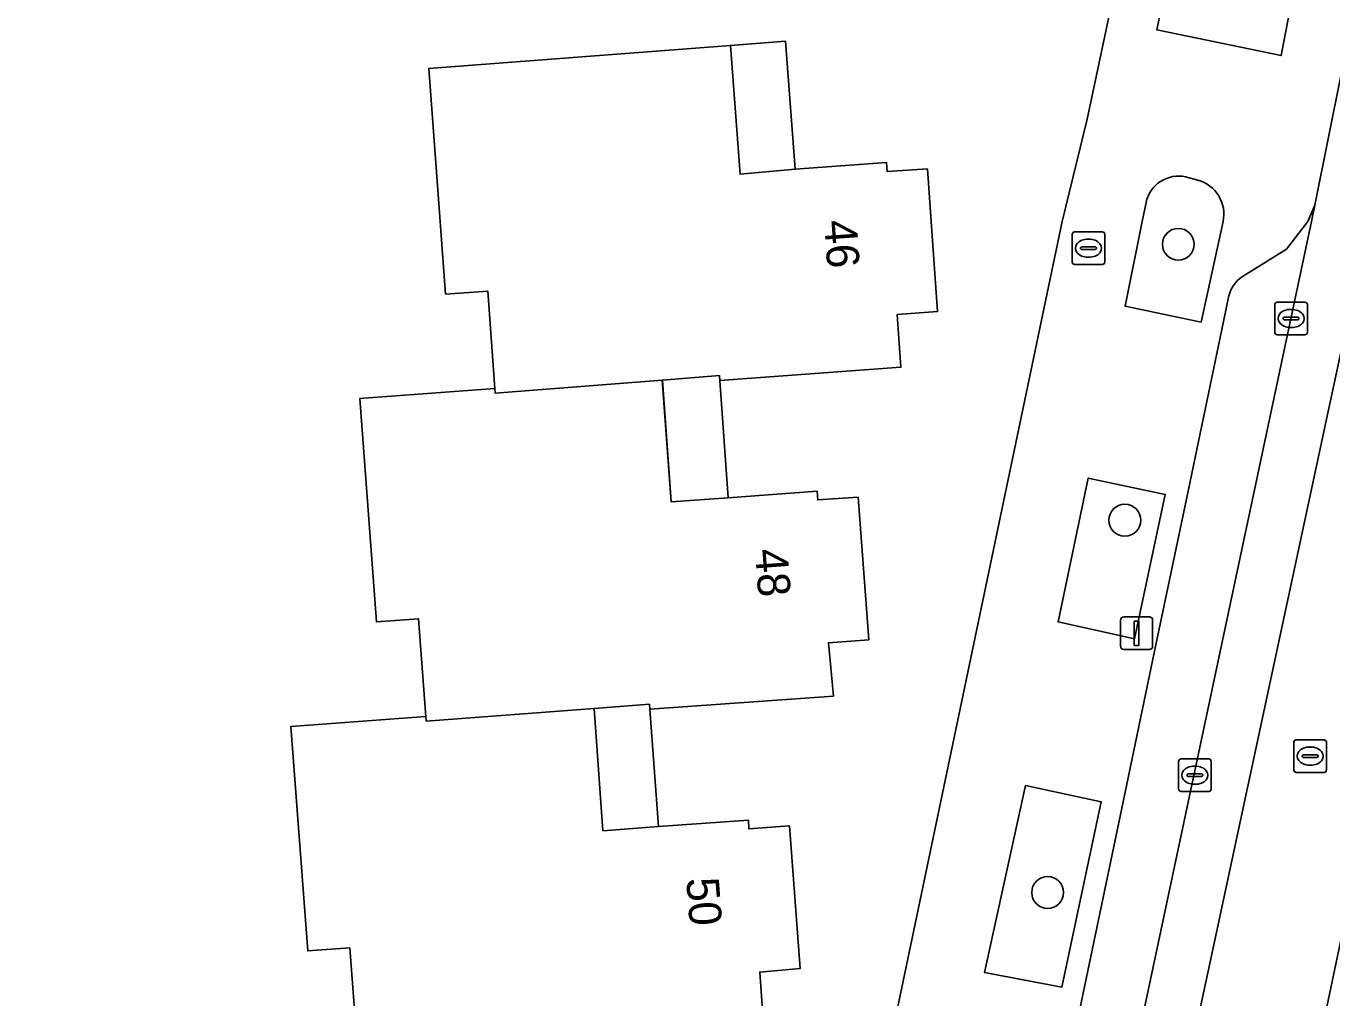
# Model space of a CAD drawing. Extents: x 163426 to 164192, y 380329 to 381641.
# Drawn here: x 163845.09 to 163885.21, y 380976.16 to 381006 of the extents above; entities that cross this region are included whole.
import ezdxf

# ---------------------------------------------------------------- set-up
doc = ezdxf.new("R2010")
doc.units = 0
for name, color, linetype in [('IMGEO_Boom', 7, 'Continuous'), ('IMGEO_Brandkraan', 7, 'Continuous'), ('IMGEO_Erf', 7, 'Continuous'), ('IMGEO_Groenvoorziening', 7, 'Continuous'), ('IMGEO_Kolk', 7, 'Continuous'), ('IMGEO_Lichtmast', 7, 'Continuous'), ('IMGEO_Pand', 7, 'Continuous'), ('IMGEO_Pand_nummerreeks', 7, 'Continuous'), ('IMGEO_Pand_overbouw', 7, 'Continuous'), ('IMGEO_Parkeervlak_open', 7, 'Continuous'), ('IMGEO_Rijbaan_lokaal_open', 7, 'Continuous'), ('IMGEO_Rioolput', 7, 'Continuous'), ('IMGEO_Voetpad_open', 7, 'Continuous')]:
    doc.layers.add(name, color=color, linetype=linetype)

msp = doc.modelspace()

# ---------------------------------------------------------------- linework, layer by layer
at = {"layer": 'IMGEO_Boom'}
for centre in [(163880.488, 380999.302), (163878.846, 380990.828), (163876.474, 380979.396)]:
    msp.add_circle(centre, 0.489, dxfattribs=at)
at = {"layer": 'IMGEO_Brandkraan'}
for p, q in [((163877.229, 380998.756), (163877.229, 380999.608)), ((163877.304, 380999.682), (163878.156, 380999.682)), ((163877.717, 380999.462), (163877.742, 380999.462)), ((163878.23, 380999.608), (163878.23, 380998.756)), ((163877.488, 380999.176), (163877.488, 380999.188)), ((163877.926, 380999.139), (163877.528, 380999.139)), ((163877.531, 380999.225), (163877.929, 380999.225)), ((163877.972, 380999.188), (163877.972, 380999.176)), ((163878.156, 380998.682), (163877.304, 380998.682)), ((163877.74, 380998.902), (163877.715, 380998.902))]:
    msp.add_line(p, q, dxfattribs=at)
for points in [[(163877.229, 380998.756), (163877.229, 380999.608)], [(163877.304, 380999.682), (163878.156, 380999.682)], [(163878.23, 380999.608), (163878.23, 380998.756)], [(163878.156, 380998.682), (163877.304, 380998.682)]]:
    msp.add_lwpolyline(points, dxfattribs=at)
for centre, radius, start, end in [((163877.306, 380999.606), 0.0765, 91.552, 178.448), ((163877.306, 380999.606), 0.0765, 91.552, 178.448), ((163878.154, 380999.606), 0.0765, 1.552, 88.448), ((163878.154, 380999.606), 0.0765, 1.552, 88.448), ((163877.528, 380999.185), 0.0403, 85.8775, 175.7526), ((163877.525, 380999.175), 0.0366, 178.938, 274.7102), ((163877.929, 380999.182), 0.043, 264.8664, 352.4533), ((163877.933, 380999.187), 0.0386, 1.7309, 96.639), ((163877.306, 380998.758), 0.0765, 181.552, 268.448), ((163877.306, 380998.758), 0.0765, 181.552, 268.448), ((163878.154, 380998.758), 0.0765, 271.552, 358.448), ((163878.154, 380998.758), 0.0765, 271.552, 358.448)]:
    msp.add_arc(centre, radius, start, end, dxfattribs=at)
for centre, major_axis, ratio, start_param, end_param in [((163877.716, 380999.182), (-0.387, 0.002), 0.722429, 4.712389, 7.853982), ((163877.741, 380999.182), (-0.39, 0.002), 0.717154, 1.570796, 4.712389)]:
    msp.add_ellipse(centre, major_axis=major_axis, ratio=ratio, start_param=start_param, end_param=end_param, dxfattribs=at)
at = {"layer": 'IMGEO_Erf'}
for points in [[(163876.92, 381000), (163877.694, 381003.139), (163878.337, 381006.181), (163878.606, 381007.454), (163876.484, 381007.934), (163866.201, 381009.23), (163857.633, 381009.637), (163842.019, 381008.688), (163839.157, 381008.481), (163804.103, 381005.949), (163804.54, 381000), (163809.124, 380937.572)], [(163855.262, 380974.705), (163855.037, 380977.702), (163853.743, 380977.604), (163853.224, 380984.493), (163857.375, 380984.806), (163857.149, 380987.803), (163855.855, 380987.705), (163855.347, 380994.567), (163859.496, 380994.875), (163859.275, 380997.867), (163857.978, 380997.771), (163857.834, 380999.717), (163857.813, 381000), (163857.465, 381004.703), (163866.73, 381005.41), (163867.025, 381001.45), (163868.714, 381001.607), (163871.527, 381001.818), (163871.543, 381001.538), (163872.78, 381001.617), (163872.894, 381000), (163873.088, 380997.235), (163871.849, 380997.145), (163871.967, 380995.526), (163866.4, 380995.119), (163866.389, 380995.269), (163864.642, 380995.131), (163864.637, 380995.131), (163864.91, 380991.393), (163866.663, 380991.521), (163869.391, 380991.72), (163869.411, 380991.451), (163870.65, 380991.541), (163870.979, 380987.158), (163869.739, 380987.068), (163869.895, 380985.426), (163864.257, 380985.029), (163864.246, 380985.179), (163862.54, 380985.049), (163862.813, 380981.295), (163864.52, 380981.419), (163867.28, 380981.62), (163867.3, 380981.35), (163868.54, 380981.44), (163868.868, 380977.059), (163867.632, 380976.955), (163867.744, 380975.339)], [(163865.188, 380943.961), (163876.92, 381000)]]:
    msp.add_lwpolyline(points, dxfattribs=at)
at = {"layer": 'IMGEO_Groenvoorziening'}
for points in [[(163883.65, 381005.095), (163884.459, 381009.317), (163880.64, 381009.791), (163879.831, 381005.887)], [(163879.148, 380987.189), (163880.09, 380991.621), (163877.721, 380992.125), (163876.796, 380987.708)], [(163876.909, 380976.494), (163878.124, 380982.184), (163875.792, 380982.681), (163874.533, 380976.942)]]:
    msp.add_lwpolyline(points, close=True, dxfattribs=at)
for points in [[(163881.088, 381001.269), (163880.713, 381001.374)], [(163879.497, 381000.588), (163879.378, 381000), (163878.853, 380997.401), (163881.191, 380996.913), (163881.865, 381000)]]:
    msp.add_lwpolyline(points, dxfattribs=at)
for centre, radius, start, end in [((163880.498, 381000.374), 1.023, 77.8442, 167.9115), ((163880.812, 381000.228), 1.077, 347.7899, 75.1678)]:
    msp.add_arc(centre, radius, start, end, dxfattribs=at)
at = {"layer": 'IMGEO_Kolk'}
for p, q in [((163883.452, 380996.598), (163883.452, 380997.45)), ((163883.527, 380997.524), (163884.379, 380997.524)), ((163884.453, 380997.45), (163884.453, 380996.598)), ((163883.711, 380997.018), (163883.711, 380997.03)), ((163883.754, 380997.067), (163884.152, 380997.067)), ((163883.94, 380997.304), (163883.965, 380997.304)), ((163884.195, 380997.03), (163884.195, 380997.018)), ((163884.149, 380996.981), (163883.751, 380996.981)), ((163883.963, 380996.744), (163883.938, 380996.744)), ((163884.379, 380996.524), (163883.527, 380996.524)), ((163880.498, 380982.573), (163880.498, 380983.425)), ((163880.573, 380983.499), (163881.425, 380983.499)), ((163881.499, 380983.425), (163881.499, 380982.573)), ((163880.757, 380982.993), (163880.757, 380983.005)), ((163880.8, 380983.042), (163881.198, 380983.042)), ((163880.986, 380983.279), (163881.011, 380983.279)), ((163881.241, 380983.005), (163881.241, 380982.993)), ((163881.195, 380982.956), (163880.797, 380982.956)), ((163881.009, 380982.719), (163880.984, 380982.719)), ((163881.425, 380982.499), (163880.573, 380982.499))]:
    msp.add_line(p, q, dxfattribs=at)
for points in [[(163883.452, 380996.598), (163883.452, 380997.45)], [(163883.527, 380997.524), (163884.379, 380997.524)], [(163884.453, 380997.45), (163884.453, 380996.598)], [(163884.379, 380996.524), (163883.527, 380996.524)], [(163880.498, 380982.573), (163880.498, 380983.425)], [(163880.573, 380983.499), (163881.425, 380983.499)], [(163881.499, 380983.425), (163881.499, 380982.573)], [(163881.425, 380982.499), (163880.573, 380982.499)]]:
    msp.add_lwpolyline(points, dxfattribs=at)
for centre, radius, start, end in [((163883.529, 380997.448), 0.0765, 91.552, 178.448), ((163883.529, 380997.448), 0.0765, 91.552, 178.448), ((163884.377, 380997.448), 0.0765, 1.552, 88.448), ((163884.377, 380997.448), 0.0765, 1.552, 88.448), ((163883.751, 380997.027), 0.0403, 85.8775, 175.7526), ((163884.156, 380997.029), 0.0386, 1.7309, 96.639), ((163883.748, 380997.017), 0.0366, 178.938, 274.7102), ((163884.152, 380997.024), 0.043, 264.8664, 352.4533), ((163883.529, 380996.6), 0.0765, 181.552, 268.448), ((163883.529, 380996.6), 0.0765, 181.552, 268.448), ((163884.377, 380996.6), 0.0765, 271.552, 358.448), ((163884.377, 380996.6), 0.0765, 271.552, 358.448), ((163880.575, 380983.423), 0.0765, 91.552, 178.448), ((163880.575, 380983.423), 0.0765, 91.552, 178.448), ((163881.423, 380983.423), 0.0765, 1.552, 88.448), ((163881.423, 380983.423), 0.0765, 1.552, 88.448), ((163880.797, 380983.002), 0.0403, 85.8775, 175.7526), ((163880.794, 380982.992), 0.0366, 178.938, 274.7102), ((163881.198, 380982.999), 0.043, 264.8664, 352.4533), ((163881.202, 380983.004), 0.0386, 1.7309, 96.639), ((163880.575, 380982.575), 0.0765, 181.552, 268.448), ((163880.575, 380982.575), 0.0765, 181.552, 268.448), ((163881.423, 380982.575), 0.0765, 271.552, 358.448), ((163881.423, 380982.575), 0.0765, 271.552, 358.448)]:
    msp.add_arc(centre, radius, start, end, dxfattribs=at)
for centre, major_axis, ratio, start_param, end_param in [((163883.939, 380997.024), (-0.387, 0.002), 0.722429, 4.712389, 7.853982), ((163883.964, 380997.024), (-0.39, 0.002), 0.717154, 1.570796, 4.712389), ((163880.985, 380982.999), (-0.387, 0.002), 0.722429, 4.712389, 7.853982), ((163881.01, 380982.999), (-0.39, 0.002), 0.717154, 1.570796, 4.712389)]:
    msp.add_ellipse(centre, major_axis=major_axis, ratio=ratio, start_param=start_param, end_param=end_param, dxfattribs=at)
at = {"layer": 'IMGEO_Lichtmast'}
for p, q in [((163878.811, 380987.858), (163879.601, 380987.858)), ((163879.601, 380987.858), (163878.811, 380987.858)), ((163878.711, 380986.958), (163878.711, 380987.758)), ((163878.711, 380987.758), (163878.711, 380986.958)), ((163879.701, 380987.758), (163879.701, 380986.958)), ((163879.701, 380986.958), (163879.701, 380987.758)), ((163879.601, 380986.858), (163878.811, 380986.858)), ((163878.811, 380986.858), (163879.601, 380986.858))]:
    msp.add_line(p, q, dxfattribs=at)
msp.add_lwpolyline([(163879.131, 380987.733), (163879.281, 380987.733), (163879.281, 380986.983), (163879.131, 380986.983), (163879.131, 380987.733)], dxfattribs=at)
for centre, start, end in [((163878.811, 380987.758), 90, 180), ((163878.811, 380987.758), 90, 180), ((163879.601, 380987.758), 0, 90), ((163879.601, 380987.758), 360, 90), ((163878.811, 380986.958), 180, 270), ((163878.811, 380986.958), 180, 270), ((163879.601, 380986.958), 270, 0), ((163879.601, 380986.958), 270, 0)]:
    msp.add_arc(centre, 0.1, start, end, dxfattribs=at)
at = {"layer": 'IMGEO_Pand'}
for points in [[(163872.894, 381000), (163872.78, 381001.617), (163871.543, 381001.538), (163871.527, 381001.818), (163868.714, 381001.607), (163867.025, 381001.45), (163866.73, 381005.41), (163857.465, 381004.703), (163857.813, 381000), (163857.834, 380999.717), (163857.978, 380997.771), (163859.275, 380997.867), (163859.496, 380994.875), (163859.507, 380994.725), (163864.637, 380995.131), (163864.642, 380995.131), (163866.389, 380995.269), (163866.4, 380995.119), (163871.967, 380995.526), (163871.849, 380997.145), (163873.088, 380997.235)], [(163870.65, 380991.541), (163869.411, 380991.451), (163869.391, 380991.72), (163866.663, 380991.521), (163864.91, 380991.393), (163864.637, 380995.131), (163859.507, 380994.725), (163859.496, 380994.875), (163855.347, 380994.567), (163855.855, 380987.705), (163857.149, 380987.803), (163857.375, 380984.806), (163857.386, 380984.656), (163862.54, 380985.049), (163864.246, 380985.179), (163864.257, 380985.029), (163869.895, 380985.426), (163869.739, 380987.068), (163870.979, 380987.158)], [(163868.54, 380981.44), (163867.3, 380981.35), (163867.28, 380981.62), (163864.52, 380981.419), (163862.813, 380981.295), (163862.54, 380985.049), (163857.386, 380984.656), (163857.375, 380984.806), (163853.224, 380984.493), (163853.743, 380977.604), (163855.037, 380977.702), (163855.262, 380974.705), (163855.273, 380974.555), (163860.383, 380974.965), (163862.17, 380975.108), (163862.18, 380974.958), (163867.744, 380975.339), (163867.632, 380976.955), (163868.868, 380977.059)]]:
    msp.add_lwpolyline(points, close=True, dxfattribs=at)
at = {"layer": 'IMGEO_Pand_overbouw'}
for points in [[(163868.423, 381005.539), (163866.73, 381005.41), (163867.025, 381001.45), (163868.714, 381001.607)], [(163866.4, 380995.119), (163866.389, 380995.269), (163864.642, 380995.131), (163864.91, 380991.393), (163866.663, 380991.521)], [(163864.257, 380985.029), (163864.246, 380985.179), (163862.54, 380985.049), (163862.813, 380981.295), (163864.52, 380981.419)]]:
    msp.add_lwpolyline(points, close=True, dxfattribs=at)
at = {"layer": 'IMGEO_Parkeervlak_open'}
for points in [[(163871.235, 380943.025), (163871.818, 380942.17), (163872.13, 380941.399), (163884.581, 381000), (163884.686, 381000.503), (163884.467, 381000), (163883.812, 380999.156), (163882.458, 380998.308)], [(163882.033, 380997.683), (163881.824, 380996.682), (163880.747, 380991.523), (163879.813, 380987.049), (163878.745, 380981.931), (163877.571, 380976.307), (163876.5, 380971.174), (163875.471, 380966.247), (163874.398, 380961.105), (163873.372, 380956.191), (163872.298, 380951.042), (163870.868, 380944.192)]]:
    msp.add_lwpolyline(points, dxfattribs=at)
msp.add_arc((163883.02, 380997.469), 1.01, 123.8113, 167.7573, dxfattribs=at)
at = {"layer": 'IMGEO_Rijbaan_lokaal_open'}
for points in [[(163921.638, 381053.716), (163922.311, 381054.818), (163921.501, 381055.887), (163917.721, 381049.86), (163902.377, 381023.75), (163895.208, 381011.818), (163892.059, 381006.187), (163890.987, 381003.841), (163890.009, 380999.579), (163886.502, 380982.789), (163875.39, 380930.027), (163874.806, 380927.256), (163873.655, 380925.227), (163872.124, 380924.818), (163868.839, 380925.415), (163868.546, 380923.98), (163875.141, 380922.738), (163879.435, 380943.25), (163880.93, 380950.483), (163883.139, 380961.124), (163886.682, 380977.995), (163888.743, 380987.877), (163891.335, 381000), (163891.536, 381000.938)], [(163909.614, 381043.056), (163891.389, 381012.622), (163887.972, 381006.053), (163887.168, 381003.975), (163886.431, 381000.422), (163877.536, 380958.937), (163873.3, 380937.44), (163872.302, 380935.525), (163871.122, 380934.091), (163870.508, 380933.6), (163868.839, 380925.415), (163872.124, 380924.818), (163873.655, 380925.227), (163874.806, 380927.256), (163875.39, 380930.027), (163886.502, 380982.789), (163890.009, 380999.579), (163890.987, 381003.841), (163892.059, 381006.187), (163895.208, 381011.818), (163902.377, 381023.75)], [(163891.645, 381015.924), (163889.16, 381011.709), (163886.918, 381007.848), (163885.783, 381005.944), (163885.735, 381005.705), (163885.507, 381004.574), (163884.686, 381000.503), (163884.581, 381000), (163872.13, 380941.399), (163871.353, 380937.742), (163870.508, 380933.6), (163871.122, 380934.091), (163872.302, 380935.525), (163873.3, 380937.44), (163877.536, 380958.937), (163886.431, 381000.422)]]:
    msp.add_lwpolyline(points, dxfattribs=at)
at = {"layer": 'IMGEO_Rioolput'}
for p, q in [((163884.039, 380983.159), (163884.039, 380984.011)), ((163884.114, 380984.085), (163884.966, 380984.085)), ((163884.527, 380983.865), (163884.552, 380983.865)), ((163885.04, 380984.011), (163885.04, 380983.159)), ((163884.298, 380983.579), (163884.298, 380983.591)), ((163884.736, 380983.542), (163884.338, 380983.542)), ((163884.341, 380983.628), (163884.739, 380983.628)), ((163884.782, 380983.591), (163884.782, 380983.579)), ((163884.966, 380983.085), (163884.114, 380983.085)), ((163884.55, 380983.305), (163884.525, 380983.305))]:
    msp.add_line(p, q, dxfattribs=at)
for points in [[(163884.039, 380983.159), (163884.039, 380984.011)], [(163884.114, 380984.085), (163884.966, 380984.085)], [(163885.04, 380984.011), (163885.04, 380983.159)], [(163884.966, 380983.085), (163884.114, 380983.085)]]:
    msp.add_lwpolyline(points, dxfattribs=at)
for centre, radius, start, end in [((163884.116, 380984.009), 0.0765, 91.552, 178.448), ((163884.116, 380984.009), 0.0765, 91.552, 178.448), ((163884.964, 380984.009), 0.0765, 1.552, 88.448), ((163884.964, 380984.009), 0.0765, 1.552, 88.448), ((163884.338, 380983.588), 0.0403, 85.8775, 175.7526), ((163884.335, 380983.578), 0.0366, 178.938, 274.7102), ((163884.739, 380983.585), 0.043, 264.8664, 352.4533), ((163884.743, 380983.59), 0.0386, 1.7309, 96.639), ((163884.116, 380983.161), 0.0765, 181.552, 268.448), ((163884.116, 380983.161), 0.0765, 181.552, 268.448), ((163884.964, 380983.161), 0.0765, 271.552, 358.448), ((163884.964, 380983.161), 0.0765, 271.552, 358.448)]:
    msp.add_arc(centre, radius, start, end, dxfattribs=at)
for centre, major_axis, ratio, start_param, end_param in [((163884.526, 380983.585), (-0.387, 0.002), 0.722429, 4.712389, 7.853982), ((163884.551, 380983.585), (-0.39, 0.002), 0.717154, 1.570796, 4.712389)]:
    msp.add_ellipse(centre, major_axis=major_axis, ratio=ratio, start_param=start_param, end_param=end_param, dxfattribs=at)
at = {"layer": 'IMGEO_Voetpad_open'}
for points in [[(163882.458, 380998.308), (163883.812, 380999.156), (163884.467, 381000), (163884.686, 381000.503), (163885.507, 381004.574), (163885.735, 381005.705), (163885.783, 381005.944), (163886.918, 381007.848), (163886.06, 381008.29), (163886.47, 381009.062), (163884.459, 381009.317), (163883.65, 381005.095), (163879.831, 381005.887), (163880.64, 381009.791), (163879.13, 381009.932), (163878.606, 381007.454), (163878.337, 381006.181), (163877.694, 381003.139), (163876.92, 381000), (163865.188, 380943.961)], [(163880.713, 381001.374), (163881.088, 381001.269)], [(163878.853, 380997.401), (163879.378, 381000), (163879.497, 381000.588)], [(163881.865, 381000), (163881.191, 380996.913), (163878.853, 380997.401)], [(163877.571, 380976.307), (163878.745, 380981.931), (163879.813, 380987.049), (163880.747, 380991.523), (163881.824, 380996.682), (163882.033, 380997.683)], [(163870.868, 380944.192), (163872.298, 380951.042), (163873.372, 380956.191), (163874.398, 380961.105), (163875.471, 380966.247), (163876.5, 380971.174), (163877.571, 380976.307)]]:
    msp.add_lwpolyline(points, dxfattribs=at)
for points in [[(163876.796, 380987.708), (163877.721, 380992.125), (163880.09, 380991.621), (163879.148, 380987.189)], [(163874.533, 380976.942), (163875.792, 380982.681), (163878.124, 380982.184), (163876.909, 380976.494)]]:
    msp.add_lwpolyline(points, close=True, dxfattribs=at)
for centre, radius, start, end in [((163880.498, 381000.374), 1.023, 77.8442, 167.9115), ((163880.812, 381000.228), 1.077, 347.7899, 75.1678), ((163883.02, 380997.469), 1.01, 123.8113, 167.7573)]:
    msp.add_arc(centre, radius, start, end, dxfattribs=at)

# ---------------------------------------------------------------- texts
at = {"layer": 'IMGEO_Pand_nummerreeks'}
for s, rotation, p in [('46', 274.022, (163869.605, 381000.022)), ('48', 274.2912, (163867.482, 380989.925)), ('50', 274.2798, (163865.371, 380979.826))]:
    msp.add_text(s, height=1, rotation=rotation, dxfattribs=at).set_placement(p)

doc.saveas('drawing.dxf')
